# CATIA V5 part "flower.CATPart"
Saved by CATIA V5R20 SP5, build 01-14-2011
Part number: flower
Material "Water": density 1000 kg/m3
Material "Multicoloured Flag"
Material "Brass": density 8216 kg/m3, Young's modulus 1.31e+11 Pa, Poisson ratio 0.35, thermal expansion 1.67e-05 1/K
Bounding box of the stored display mesh (mm): x -45.563 to 45.563, y -45.563 to 61.991, z 0 to 139.66
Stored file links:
  D:\3D工程制图\180132104于洋\flower.CATPart
  C:\Program Files\Dassault Systemes\B20\intel_a\startup\materials\Catalog.CATMaterial
  C:\Program Files\Dassault Systemes\B20\intel_a\startup\materials\teak_2.jpg
  C:\Program Files\Dassault Systemes\B20\intel_a\startup\materials\cedar.jpg
  C:\Program Files\Dassault Systemes\B20\intel_a\startup\materials\blue_env_512x512.jpg
  C:\Program Files\Dassault Systemes\B20\intel_a\startup\materials\DS_star.jpg
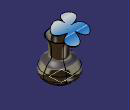
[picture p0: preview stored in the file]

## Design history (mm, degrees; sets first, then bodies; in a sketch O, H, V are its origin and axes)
Body1 (main body), material "Brass"
  Plane1: type Offset, RefPlane xy-plane, Offset 20
  Plane2: type Offset, RefPlane Plane1, Offset 20
  Plane3: type Offset, RefPlane Plane2, Offset 20
  Plane4: type Offset, RefPlane Plane3, Offset 20
  Plane5: type Offset, RefPlane Plane4, Offset 20
  Sketch1 on Plane5, origin (0, 0, 100), H (1, 0, 0), V (0, 1, 0)
    circle A1 centre (0, 0) radius 29.8266
  Sketch2 on Plane4, origin (0, 0, 80), H (1, 0, 0), V (0, 1, 0)
    circle A1 centre (0, 0) radius 23.0726
  Sketch3 on Plane3, origin (0, 0, 60), H (1, 0, 0), V (0, 1, 0)
    circle A1 centre (0, 0) radius 21.9749
  Sketch4 on Plane2, origin (0, 0, 40), H (1, 0, 0), V (0, 1, 0)
    circle A1 centre (0, 0) radius 37.8812
  Sketch5 on Plane1, origin (0, 0, 20), H (1, 0, 0), V (0, 1, 0)
    circle A1 centre (0, 0) radius 45.607
  Sketch6 on xy-plane, origin (0, 0, 0), H (1, 0, 0), V (0, 1, 0)
    circle A1 centre (0, 0) radius 31.6229
  Loft1: solid, Sections (Sketch1; Sketch2; Sketch3; Sketch4; Sketch5; Sketch6)
  Shell1: ExtOffset 0, Face face of Loft1, IntOffset 1
Body2, material "Water"
  Sketch7 on yz-plane, origin (0, 0, 0), H (0, 1, 0), V (0, 0, 1)
    axis line L1 (0, 117.0904) -> (0, -14.88)
    point P1 (0, 117.0904)
    line L2 (0, 0) -> (30.5626, 0)
    line L3 (30.5626, 0) -> (41.5502, 9.897)
    line L4 (41.5502, 9.897) -> (44.4279, 15.6349)
    line L5 (44.4279, 15.6349) -> (44.4279, 21.6335)
    line L6 (44.4279, 21.6335) -> (43.1199, 28.9362)
    line L7 (43.1199, 28.9362) -> (0, 28.9362)
    point P8 (0, 28.9362)
    line L8 (0, 28.9362) -> (0, 0)
    coincidence: P1 V, P8 L1
    vertical: L1 V, L5 V, L8 V
    horizontal: L2 H, L7 H
  Shaft1: profile Sketch7, axis Sketch7.L1, angle 360
Body3, material "Multicoloured Flag"
  Sketch8 on yz-plane, origin (0, 0, 0), H (0, 1, 0), V (0, 0, 1)
    spline S1 through (4.925, 3.3767) (15.651, 101.1809) (24.5457, 125.9579)
    point P1 (24.5457, 125.9579)
    point P2 (24.5457, 125.9579)
    coincidence: P1 P2
  Plane6: type Normal, Curve Sketch8, RefPoint vertex of Sketch8
  Sketch9 on Plane6, origin (0, -0.2087, 3.0221), H (-1, 0, 0), V (0, 0.9976, 0.0689)
    circle A1 centre (0, 4.9123) radius 1
    point P1 (0, 4.9123)
    radius A1 = 1
    coincidence: P1 V
  Rib1: profile Sketch9, centre curve Sketch8
  Plane7: type OffsetPt, RefPlane zx-plane, RefPoint Sketch8.P2
  Plane8: type Normal, Curve Sketch8, RefPoint Sketch8.P2
  Sketch10 on Plane8, origin (0, 48.2205, 116.1272), H (1, 0, 0), V (0, -0.9235, 0.3835)
    spline S1 through (-4.3423, 41.7545) (-19.2273, 61.1433) (-37.8855, 41.7545) (-12.0228, 30.6751) (-40.4521, 21.5134) (-23.8706, -3.9187) (-8.5786, 13.9217) (2.1878, -12.1777) (28.996, 6.7624) (7.7842, 19.0587) (34.5873, 27.8468) (18.1132, 54.0973) (-4.3423, 41.7545)
    point P1 (-4.3423, 41.7545)
    point P2 (-4.3423, 41.7545)
    coincidence: P1 P2
  Pad1: profile Sketch10, direction (0, -0.3835, -0.9235), length 1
